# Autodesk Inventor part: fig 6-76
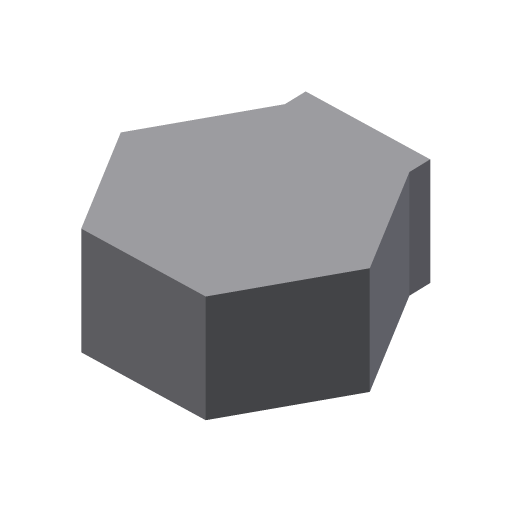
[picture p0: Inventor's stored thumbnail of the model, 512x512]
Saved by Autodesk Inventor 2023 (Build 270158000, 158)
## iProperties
Created: 2009-03
Part Number: fig 6-76
Document SubType Name: Modeling
Designer: Sham
Density: 1 g/cm^3
Material: Generic
Appearance: Default
Author: Sham
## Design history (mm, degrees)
sketch "Sketch5"
  geometry: L1 (-5.929, 9.627)-(5.372, 9.948); L2 (5.372, 9.948)-(11.301, 0.321); L3 (11.301, 0.321)-(5.929, -9.627); L4 (5.929, -9.627)-(-5.372, -9.948); L5 (-5.372, -9.948)-(-11.301, -0.321); L6 (-11.301, -0.321)-(-5.929, 9.627); 1 further point
  constraints: 12 end point, 13 other
extrude "Extrusion3" new body sketch "Sketch5" distance "d13" = 10; taper "d14" = 0 deg
thicken "Thicken2" dims "d15" = 2, "d16" = 2
body "Solid4"
